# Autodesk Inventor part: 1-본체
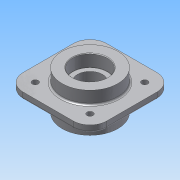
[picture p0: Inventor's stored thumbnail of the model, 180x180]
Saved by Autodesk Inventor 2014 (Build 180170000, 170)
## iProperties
Created: 2015-09
Part Number: 1-본체
Material: 알루미늄 6061
Document SubType Name: Modeling
Designer: study
Density: 2.70916 g/cm^3
Appearance: 알루미늄 - 평지
Mass: 1467 g
Surface Area: 792.775 cm^2
Volume: 541.496 cm^3
Author: study
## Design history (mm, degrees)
sketch "스케치1"
  geometry: L1 (-75, 75)-(75, 75); L2 (75, 75)-(75, -75); L3 (75, -75)-(-75, -75); L4 (-75, -75)-(-75, 75); L5 (-75, 75)-(75, -75); L6 (75, 75)-(-75, -75); 1 further point
  constraints: 12 end point, 2 midpoint, 2 parallel, 1 horizontal, 1 perpendicular
  dimensions: "d0" = 150 distance of L2.end L3.end; "d1" = 150 distance of L1.end L2.end
extrude "돌출1" new body sketch "스케치1" stored distance "d2" = 12; taper "d3" = 0 deg
sketch "스케치2"
  geometry: C1 r 50 at (0, 0); 1 further point
  constraints: 1 centre point, 1 coincident
  dimensions: "d4" = 100 diameter of C1
extrude "돌출2" join sketch "스케치2" distance "d5" = 23; taper "d6" = 0 deg
sketch "스케치3"
  geometry: C1 r 50 at (0, 0) reference; 1 further point
extrude "돌출3" join sketch "스케치3" distance "d7" = 35; taper "d8" = 0 deg
hole "구멍1" diameter "d11" = 45; stored, may be unused: countersink angle "d15" = 90 deg, drill point angle "d17" = 118 deg; dims "d9" = 10, "d10" = 10, "d12" = 6, "d13" = 62, "d14" = 22, "d16" = 8
hole "구멍2" diameter "d20" = 45; stored, may be unused: countersink angle "d24" = 90 deg, drill point angle "d26" = 118 deg; dims "d18" = 10, "d19" = 10, "d21" = 6, "d22" = 62, "d23" = 22, "d25" = 8
sketch "스케치4"
  geometry: L1 (-49, 49)-(49, 49); L2 (49, 49)-(49, -49); L3 (49, -49)-(-49, -49); L4 (-49, -49)-(-49, 49); L5 (-49, 49)-(49, -49); L6 (49, 49)-(-49, -49); C1 r 50 at (0, 0) reference; C2 r 10 at (-49, 49); C3 r 10 at (49, 49); C4 r 10 at (49, -49); C5 r 10 at (-49, -49)
  constraints: 12 end point, 4 centre point, 4 coincident, 3 equal radius, 2 midpoint, 2 parallel, 1 horizontal, 1 perpendicular
  dimensions: "d27" = 98 distance of L1.start L1.end; "d28" = 98 distance of L1.end L2.end; "d29" = 20 diameter of C2
extrude "돌출4" join sketch "스케치4" distance "d30" = 5; taper "d31" = 0 deg
sketch "스케치5" dims "d32" = 82
  geometry: L1 (0, 0)-(-72.601, 0); L2 (0, 0)-(-35.355, 35.355); 2 further points
  constraints: 4 end point, 1 coincident, 1 horizontal, 1 point on line, 5 other
  dimensions: "d33" = 45 deg angle of L1 L2
hole "구멍3" sketch "스케치5" at (-28.991, 28.991) diameter "d34" = 4.917; stored, may be unused: countersink angle "d38" = 90 deg, drill point angle "d40" = 118 deg; dims "d35" = 10, "d36" = 62, "d37" = 22, "d39" = 13
sketch "스케치6"
  geometry: C1 r 10 at (0, 0) reference; C2 r 10 at (98, 0) reference; C3 r 10 at (98, -98) reference; C4 r 10 at (0, -98) reference; 5 further points
  constraints: 4 coincident
hole "구멍4" sketch "스케치6" at (0, 0), (98, 0), (98, -98), (0, -98) diameter "d44" = 11; stored, may be unused: countersink angle "d48" = 90 deg, drill point angle "d50" = 118 deg; dims "d45" = 10, "d46" = 62, "d47" = 22, "d49" = 13
sketch "스케치7"
  geometry: C1 r 50 at (0, 0) reference; 1 further point
  constraints: 1 vertical alignment, 1 other
  dimensions: "d51" = 65 distance of C1.centre point (0, 65)
feature "엠보싱1" sketch "스케치7" dims "d0" = 150, "d1" = 150, "d18" = 10, "d19" = 10, "d52" = 1, "d53" = 0
fillet "모깎기1" dims "d54" = 30
fillet "모깎기2" dims "d55" = 0.3
fillet "모깎기3" dims "d56" = 3
chamfer "모따기1" distance "d57" = 1; stored, may be unused: second distance "d58" = 2, angle "d59" = 45 deg
node "솔리드1"
pattern_circular "원형 패턴1" dims angle "d42" = 360 deg
